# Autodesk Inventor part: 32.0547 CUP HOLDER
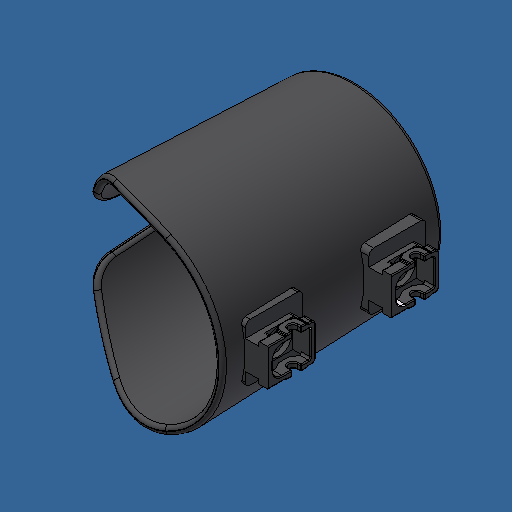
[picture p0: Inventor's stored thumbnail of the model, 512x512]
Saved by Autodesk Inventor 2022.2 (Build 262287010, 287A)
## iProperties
Created: 2014-10
Part Number: 32.0547 CUP HOLDER
Material: ABS Plastic
Document SubType Name: Modeling
Designer: Admin
Density: 1.06 g/cm^3
Mass: 145.326 g
Surface Area: 714.672 cm^2
Volume: 137.1 cm^3
Appearance: Gray
Author: Admin
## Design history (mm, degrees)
feature "Base1"
body "Solid1"
